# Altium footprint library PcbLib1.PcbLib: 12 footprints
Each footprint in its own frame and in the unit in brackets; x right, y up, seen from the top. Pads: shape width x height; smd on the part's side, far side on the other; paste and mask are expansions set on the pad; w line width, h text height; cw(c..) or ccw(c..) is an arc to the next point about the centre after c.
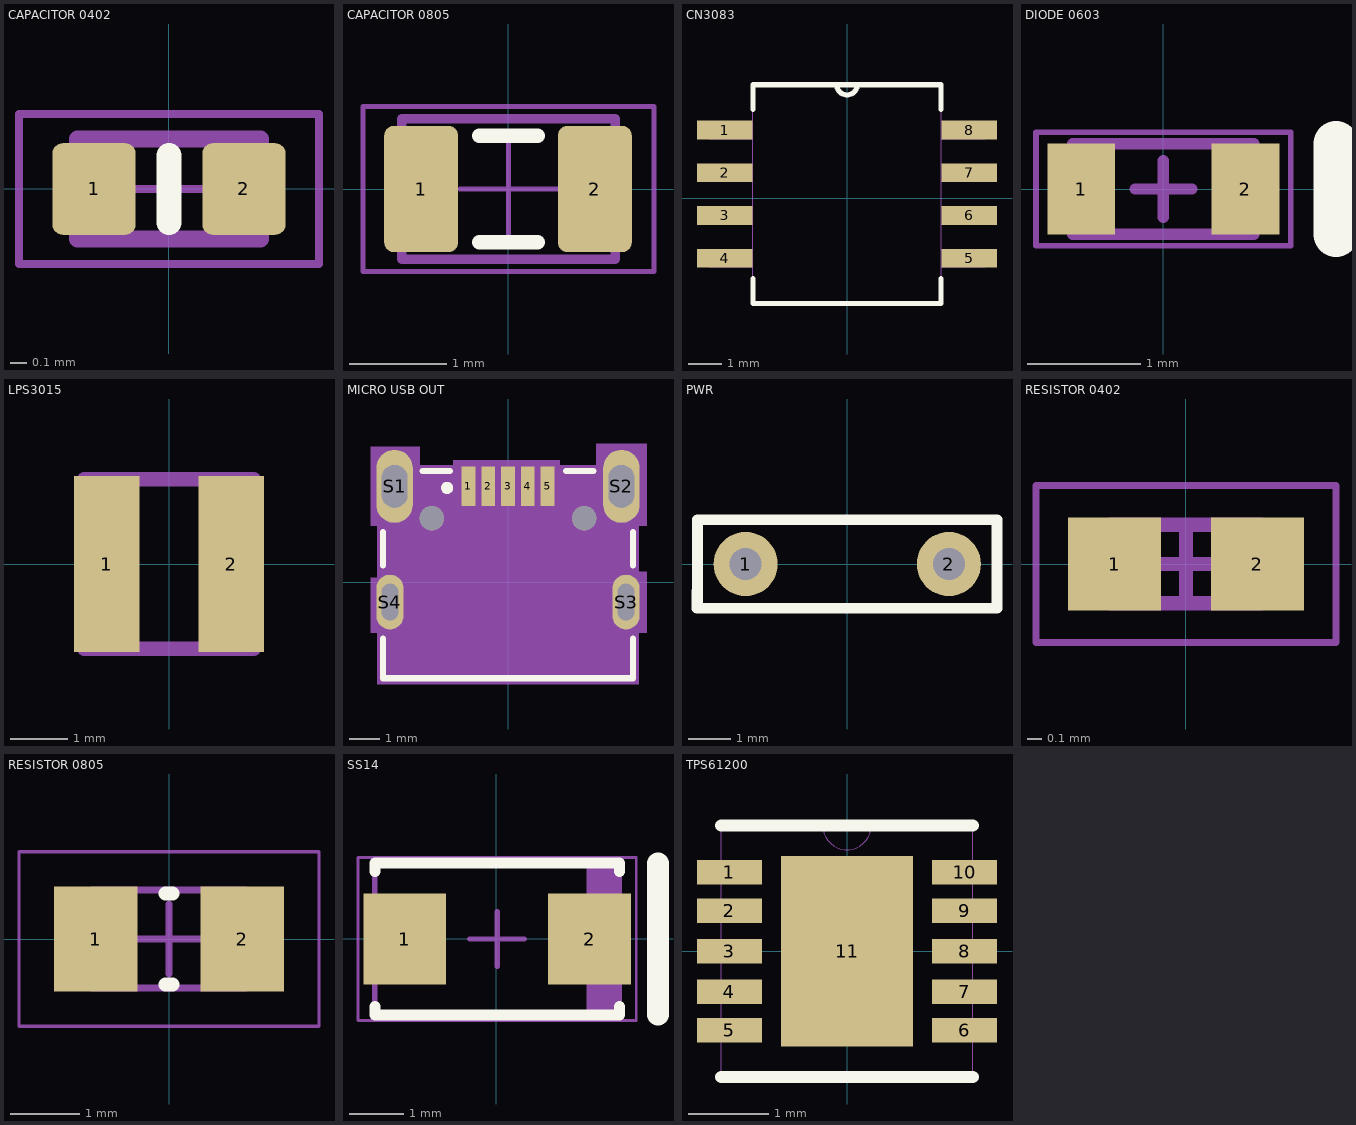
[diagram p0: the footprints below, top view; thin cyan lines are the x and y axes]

## BAT [mil]

## CAPACITOR 0402 [mm]
pads (2):
  rrect25% 0.5x0.55 smd: 1(-0.45,0) 2(0.45,0)
Top Overlay:
  lines w0.15: 0,-0.2 0,0.2
Top Courtyard:
  lines w0.05: -0.275,0 0.275,0 ; 0,-0.275 0,0.275 ; -0.9,-0.45 -0.9,0.45 0.9,0.45 0.9,-0.45 -0.9,-0.45
Top Assembly:
  lines w0.1: -0.55,-0.3 0.55,-0.3 0.55,0.3 -0.55,0.3 -0.55,-0.3
Top Designator:
  text ".Designator" at -1.27,-0.127 h0.6
3D body "CAPC1005X60N EIA 0402.STEP": height 0.6, standoff 0, extent -0.5,-0.25 0.5,0.25

## CAPACITOR 0805 [mm]
pads (2):
  rrect25% 0.76x1.3 smd: 1(-0.9,0) 2(0.89,0)
Top Overlay:
  lines w0.15: -0.3,-0.55 0.3,-0.55 ; -0.3,0.55 0.3,0.55
Top Courtyard:
  lines w0.05: -0.5,0 0.5,0 ; 0,-0.5 0,0.5 ; -1.5,-0.85 -1.5,0.85 1.5,0.85 1.5,-0.85 -1.5,-0.85
Top Assembly:
  lines w0.1: -1.1,-0.725 1.1,-0.725 1.1,0.725 -1.1,0.725 -1.1,-0.725
Top Designator:
  text ".Designator" at -1.27,-0.127 h0.6
3D body "CAPC2012X145N EIA 0805.STEP": height 1.45, standoff 0, extent -1,-0.6 1,0.6

## CN3083 [mil]
pads (8):
  rect 65x22 smd: 1(-143,80) 2(-143,30) 3(-143,-20) 4(-143,-70) 5(143,-70) 6(143,-20) 7(143,30) 8(143,80)
Top Overlay:
  lines w6: -110,-94 -110,-123 110,-123 110,-94 ; -110,104 -110,133 -12,133 ; 110,104 110,133 12,133 ; -12,133 ccw(c0,133) 12,133 ; -12,133 12,133
Mechanical 13:
  lines w0: -12,133 ccw(c0,133) 12,133 ; -12,133 -110,133 -110,-123 110,-123 110,133 12,133 ; -12,133 12,133 ; -161,-80 -110,-80 -110,-60 -161,-60 -161,-80 ; -161,-30 -110,-30 -110,-10 -161,-10 -161,-30 ; -161,20 -110,20 -110,40 -161,40 -161,20 ; -161,70 -110,70 -110,90 -161,90 -161,70 ; 110,-80 161,-80 161,-60 110,-60 110,-80 ; 110,-30 161,-30 161,-10 110,-10 110,-30 ; 110,20 161,20 161,40 110,40 110,20 ; 110,70 161,70 161,90 110,90 110,70
3D body "CN3083.stp": height 68.9, standoff 0, extent -118.11,-91.46 118.11,101.46

## DIODE 0603 [mm]
pads (2):
  rect 0.6x0.8 smd: 1(-0.725,0) 2(0.725,0)
Top Overlay:
  lines w0.4: 1.525,-0.4 1.525,0.4
Mechanical 13:
  lines w0.1: -0.8,-0.4 0.8,-0.4 0.8,0.4 -0.8,0.4 -0.8,-0.4
Mechanical 15:
  lines w0.05: -1.125,-0.5 -1.125,0.5 1.125,0.5 1.125,-0.5 -1.125,-0.5
  lines w0.1: -0.25,0 0.25,0 ; 0,-0.25 0,0.25
3D body: height 0.65, standoff 0, extent -0.8,-0.4 0.8,0.4

## LPS3015 [mm]
pads (2):
  rect 1.14x3.05 smd: 1(-1.08,0) 2(1.08,0)
Mechanical 13:
  lines w0.254: -1.475,-1.475 1.475,-1.475 1.475,1.475 -1.475,1.475 -1.475,-1.475
3D body "User Library-LPS3015.step": height 1.4, standoff 0, extent -1.426,-1.475 1.524,1.475

## MICRO USB OUT [mm]
pads (11):
  rect 0.45x1.3 smd: 1(-1.3,3.154) 2(-0.65,3.154) 3(0,3.154) 4(0.65,3.154) 5(1.3,3.154)
  oval 1.2x2.4 hole 0.85 slot 1.4 at 90 deg: S1(-3.725,3.154) S2(3.725,3.154)
  oval 0.9x1.8 hole 0.55 slot 1.2 at 90 deg: S3(3.875,-0.646) S4(-3.875,-0.646)
  round 0.8 hole 0.8 unplated: ""(-2.5,2.104) ""(2.5,2.104)
Top Overlay:
  circle w0.2: c-2,3.104 r0.1
  lines w0.2: -4.1,-1.846 -4.1,-3.146 4.1,-3.146 4.1,-1.846 ; -4.1,0.554 -4.1,1.654 ; -2.8,3.654 -1.9,3.654 ; 1.9,3.654 2.8,3.654 ; 4.1,0.554 4.1,1.654
Mechanical 1:
  lines w0.01: -4.03,-1.246 -3.72,-1.246 ; -4.03,-0.046 -3.72,-0.046 ; -4,2.454 -3.45,2.454 ; -4,3.854 -3.45,3.854 ; 3.45,2.454 4,2.454 ; 3.45,3.854 4,3.854 ; 3.72,-1.246 4.03,-1.246 ; 3.72,-0.046 4.03,-0.046
Mechanical 13:
  lines w0.1: -4,-2.446 4,-2.446 ; -4,-2.446 -4,3.554 4,3.554 4,-2.446 ; -4,-2.446 -4,-3.046 4,-3.046 4,-2.446
  text "Recommonded PCB Layout Tinckness:1.2mm" at -4.1,-3.776 h0.3
  text "PCB Edge" at -1.2,-2.276 h0.41
Mechanical 15:
  region: 4.55,1.854 4.3,1.854 4.3,0.354 4.55,0.354 4.55,-1.646 4.3,-1.646 4.3,-3.346 -4.3,-3.346 -4.3,-1.646 -4.5,-1.646 -4.5,0.154 -4.3,0.154 -4.3,1.854 -4.5,1.854 -4.5,4.454 -2.9,4.454 -2.9,3.854 -1.8,3.854 -1.8,4.004 1.7,4.004 1.7,3.854 2.9,3.854 2.9,4.554 4.55,4.554
3D body "629105150521 (rev1).stp": height 1.67, standoff -2.85, extent -4,-3.064 4,3.539

## PWR [mil]
pads (2):
  round 60 hole 30: 1(-95,0) 2(95,0)
Top Overlay:
  lines w10: -140.47,-41.3 -140.47,-25.55 ; -140,-41.3 140,-41.3 140,41.38 -140,41.38 -140,-41.3

## RESISTOR 0402 [mm]
pads (2):
  rect 0.65x0.65 smd: 1(-0.5,0) 2(0.5,0)
Mechanical 13:
  lines w0.1: -0.525,-0.275 -0.525,0.275 0.525,0.275 0.525,-0.275 -0.525,-0.275
Mechanical 15:
  lines w0.05: -1.05,-0.55 -1.05,0.55 1.05,0.55 1.05,-0.55 -1.05,-0.55
  lines w0.1: -0.275,0 0.275,0 ; 0,-0.275 0,0.275
3D body "RESC1005X04M.step": height 0.4, standoff 0, extent -0.525,-0.275 0.525,0.275

## RESISTOR 0805 [mm]
pads (2):
  rect 1.2x1.5 smd: 1(-1.05,0) 2(1.05,0)
Top Overlay:
  lines w0.2: -0.05,-0.65 0.05,-0.65 ; -0.05,0.65 0.05,0.65
Mechanical 13:
  lines w0.1: -1.1,-0.7 -1.1,0.7 1.1,0.7 1.1,-0.7 -1.1,-0.7
Mechanical 15:
  lines w0.05: -2.15,-1.25 -2.15,1.25 2.15,1.25 2.15,-1.25 -2.15,-1.25
  lines w0.1: -0.5,0 0.5,0 ; 0,-0.5 0,0.5
3D body "RESC2112X05M.step": height 0.5, standoff 0, extent -1.1,-0.7 1.1,0.7

## SS14 [mm]
pads (2):
  rect 1.52x1.68 smd: 1(-1.688,-0.006) 2(1.712,-0.006)
Top Overlay:
  lines w0.2: -2.238,-1.246 -2.238,-1.406 2.262,-1.406 2.262,-1.246 ; -2.238,1.234 -2.238,1.394 2.262,1.394 2.262,1.234
  lines w0.4: 2.972,-1.401 2.972,1.389
Mechanical 13:
  rectangle: 1.657,-1.401 2.262,1.389
  lines w0.1: -2.238,-1.401 -2.238,1.389 2.262,1.389 2.262,-1.401 -2.238,-1.401
Mechanical 15:
  lines w0.05: -2.548,-1.506 -2.548,1.494 2.572,1.494 2.572,-1.506 -2.548,-1.506
  lines w0.1: -0.488,-0.006 0.512,-0.006 ; 0.012,-0.506 0.012,0.494
3D body "DIOM4227X23L.step": height 2.29, standoff 0, extent -2.458,-1.401 2.482,1.389

## TPS61200 [mil]
pads (11):
  rect 32x12 smd: 1(-58,39) 2(-58,20) 3(-58,0) 4(-58,-20) 5(-58,-39) 6(58,-39) 7(58,-20) 8(58,0) 9(58,20) 10(58,39)
  rect 65x94 smd: 11(0,0)
Top Overlay:
  lines w6: -62,-62 62,-62 ; -62,62 62,62
Mechanical 13:
  lines w0: -12,62 ccw(c0,62) 12,62 ; -12,62 -62,62 -62,-62 62,-62 62,62 12,62 ; -12,62 12,62
3D body "DRC10_2P4X1P65.step": height 39.49, standoff 0, extent -59.02,-61.02 59.01,61.02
